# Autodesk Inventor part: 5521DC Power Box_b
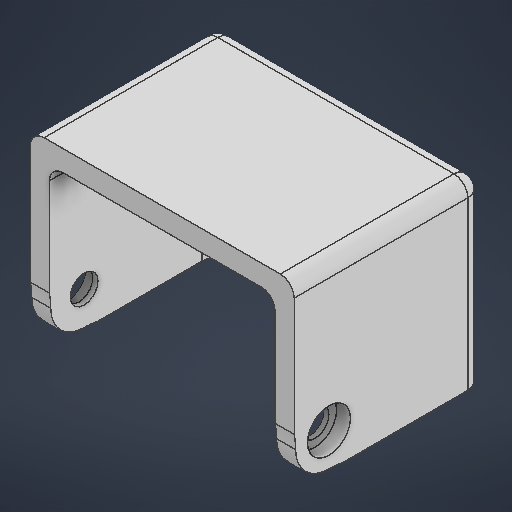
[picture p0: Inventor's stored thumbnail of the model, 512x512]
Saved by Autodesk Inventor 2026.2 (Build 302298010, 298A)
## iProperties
Created: 2026-05
Part Number: 5521DC Power Box_b
Material: 일반
Document SubType Name: Modeling
Designer: work
Density: 1 g/cm^3
Appearance: 기본값
Author: work
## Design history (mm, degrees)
sketch "스케치1"
  geometry: L1 (0, 0)-(23, 0); L2 (23, 0)-(23, -24); L3 (23, -24)-(0, -24); L4 (0, -24)-(0, 0); L5 (0, 0)-(26, 0); L6 (26, 0)-(26, -27); L7 (26, -27)-(0, -27); L8 (0, -27)-(0, 0); 3 further points
  constraints: 16 end point, 4 parallel, 2 horizontal, 2 perpendicular, 1 midpoint
  dimensions: "d0" = 23 distance of L2.end L3.end; "d1" = 24 distance of L1.end L2.end; "d2" = 3 distance from line of point (26, -13.5) L2; "d3" = 3 distance between parallel lines of L7 L3
extrude "돌출1" new body sketch "스케치1" stored distance "d4" = 38; taper "d5" = 0 deg
extrude "돌출2" cut sketch "스케치1" stored distance "d6" = 32.5; taper "d7" = 0 deg
sketch "스케치2"
  geometry: L1 (19, -26)-(19, -18); L2 (21.5, -26)-(21.5, -18); L3 (16.5, -18)-(16.5, -26); A1 r 2.5 centre (19, -26) between (16.5, -26) and (21.5, -26); A2 r 2.5 centre (19, -18) between (21.5, -18) and (16.5, -18); 1 further point
  constraints: 8 end point, 4 point on circle, 4 tangent, 2 centre point, 1 midpoint, 1 parallel, 1 vertical
  dimensions: "d8" = 2.5 radius of A2; "d9" = 8 distance of L1.start L1.end
extrude "돌출3" cut sketch "스케치2" distance "d10" = 31.5; taper "d11" = 0 deg
fillet "모깎기1" dims "d12" = 2
sketch "스케치3"
  geometry: C1 r 2 at (5, 5); 1 further point
  constraints: 1 centre point
  dimensions: "d13" = 4 diameter of C1; "d14" = 5 horizontal distance of point (0, 0) C1.centre; "d15" = 5 horizontal distance of point (0, 0) C1.centre
extrude "돌출4" cut sketch "스케치3" extent not by distance; stored distance "d16" = 0; taper "d17" = 0 deg
sketch "스케치4"
  geometry: C1 r 2 at (5, 5) reference; 2 further points
  constraints: 1 coincident
hole "구멍1" sketch "스케치4" at (5, 5) diameter "d18" = 4; stored, may be unused: countersink angle "d22" = 90 deg, drill point angle "d24" = 118 deg; dims "d19" = 6, "d20" = 6.2, "d21" = 2, "d23" = 8
sketch "스케치5"
  geometry: C1 r 2 at (-5, 5) reference; 2 further points
  constraints: 1 coincident
hole "구멍2" sketch "스케치5" at (-5, 5) diameter "d25" = 4; stored, may be unused: countersink angle "d29" = 90 deg, drill point angle "d31" = 118 deg; dims "d26" = 6, "d27" = 6.2, "d28" = 2, "d30" = 8
sketch "스케치6"
  geometry: L1 (25, 24)-(25, 0) reference; L2 (0, 24)-(25, 24) reference; L3 (0, 24)-(0, 0) reference; L4 (0, 0)-(25, 0) reference; C1 r 3.1 at (5, 5) reference; C2 r 5 at (5, 5); A1 r 4.8 centre (5, 5) between (5.005, 0.2) and (0.2, 5.005); A2 r 10 centre (5.015, -9.8) between (7.005, 0) and (5.005, 0.2); A3 r 10 centre (-9.8, 5.015) between (0.2, 5.005) and (0, 7.005); 1 further point
  constraints: 6 point on circle, 4 centre point, 3 tangent, 2 coincident, 2 point on line
  dimensions: "d32" = 0.2 radial gap between concentric circles of C2 A1; "d33" = 10 radius of A2; "d34" = 2 horizontal distance of A1.start A2.start; "d35" = 2 vertical distance of A1.end A3.end; "d36" = 10 radius of A3
extrude "돌출5" cut sketch "스케치6" extent not by distance; stored distance "d37" = 0; taper "d38" = 0 deg
fillet "모깎기2" dims "d39" = 2
node "솔리드1"
node "투영된 루프1"
feature "A9D066F2-1C7D-4E18-AEED-F7BC21143FA4" dims "d18" = 4, "d19" = 6, "d20" = 6.2, "d21" = 2, "d22" = 90 deg, "d23" = 8, "d24" = 118 deg
